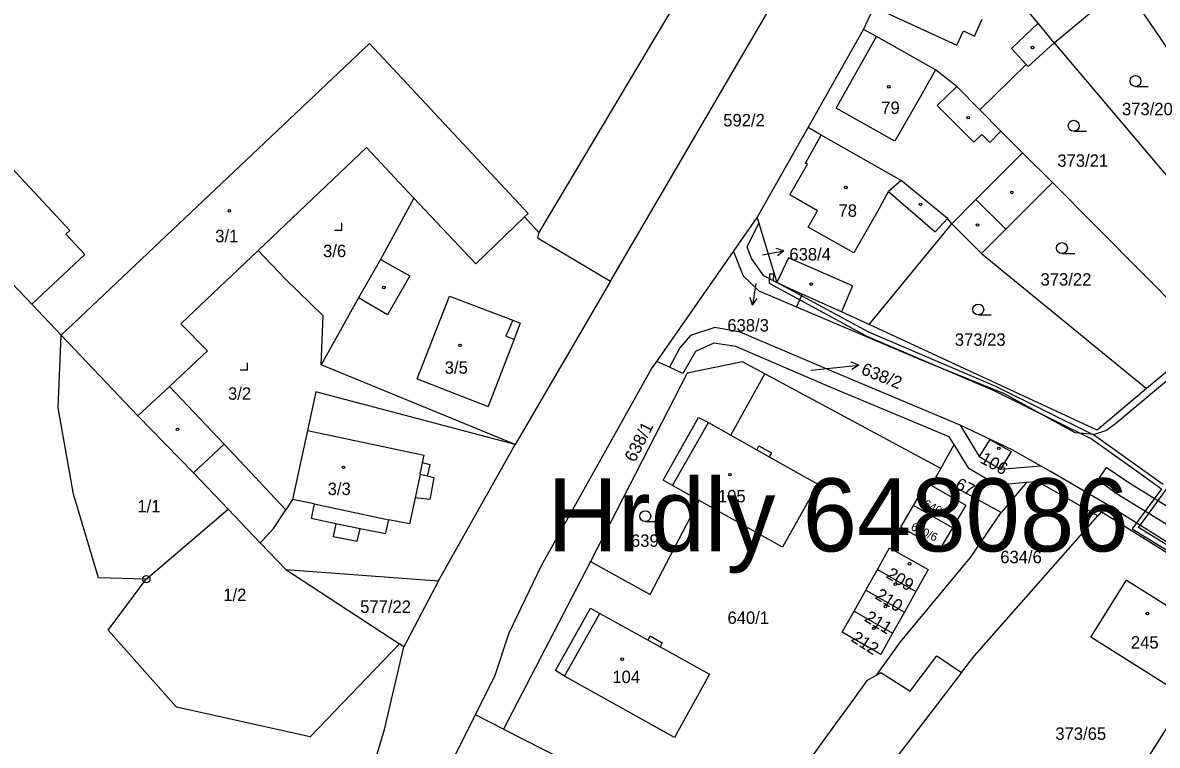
# Model space of a CAD drawing. Extents: x -758582 to -751794, y -998770 to -994350.
# Drawn here: x -754496.6 to -754341.3, y -996853.5 to -996754.5 of the extents above; entities that cross this region are included whole.
import ezdxf

# ---------------------------------------------------------------- set-up
doc = ezdxf.new("R2010")
doc.units = 0
for name, color, linetype in [('Hranice parcel', 7, 'Continuous'), ('Parcelní čísla', 7, 'Continuous'), ('Pop  PČ popisy', 7, 'Continuous'), ('Vnitřní kresba', 7, 'Continuous'), ('Věcná břemena k části', 7, 'Continuous'), ('Značky bodu BP', 7, 'Continuous'), ('Značky budov', 7, 'Continuous'), ('Značky kultur', 7, 'Continuous')]:
    doc.layers.add(name, color=color, linetype=linetype)

msp = doc.modelspace()

# ---------------------------------------------------------------- linework, layer by layer
at = {"layer": 'Hranice parcel'}
for p, q in [((-754381.5, -996755.49), (-754377.61, -996747.1)), ((-754355.4, -996757.29), (-754345.87, -996749.35)), ((-754345.87, -996749.35), (-754319.46, -996788.44)), ((-754416.14, -996789.92), (-754392.89, -996750.08)), ((-754389.1, -996768.87), (-754381.5, -996755.49)), ((-754355.4, -996757.29), (-754325.8, -996792.38)), ((-754396.07, -996781.23), (-754389.1, -996768.87)), ((-754355.66, -996776.42), (-754334.53, -996797.73)), ((-754399.32, -996785.89), (-754396.07, -996781.23)), ((-754396.07, -996781.23), (-754395.84, -996781.98)), ((-754395.84, -996781.98), (-754393.39, -996790.11)), ((-754380.75, -996795.88), (-754369.44, -996782.07)), ((-754369.44, -996782.07), (-754365.35, -996786.16)), ((-754409.82, -996800.93), (-754399.32, -996785.89)), ((-754365.35, -996786.16), (-754342.79, -996804.64)), ((-754416.14, -996789.92), (-754429.19, -996812.29)), ((-754495.35, -996793.06), (-754498.09, -996790.19)), ((-754393.39, -996790.11), (-754389.93, -996791.69)), ((-754495.35, -996793.06), (-754491.31, -996797.33)), ((-754389.93, -996791.69), (-754390.68, -996793.43)), ((-754334.53, -996797.73), (-754342.79, -996804.64)), ((-754429.19, -996812.29), (-754455.74, -996801.38)), ((-754408.09, -996801.72), (-754409.82, -996800.93)), ((-754399.66, -996811.01), (-754395, -996802.63)), ((-754370.91, -996815.57), (-754395, -996802.63)), ((-754402.75, -996809.27), (-754399.66, -996811.01)), ((-754399.66, -996811.01), (-754396.11, -996813.01)), ((-754369.13, -996812.31), (-754369.8, -996811.23)), ((-754439.66, -996830.97), (-754429.19, -996812.29)), ((-754370.91, -996815.57), (-754369.13, -996812.31)), ((-754367.12, -996815.56), (-754369.13, -996812.31)), ((-754371.55, -996816.73), (-754370.91, -996815.57)), ((-754403.99, -996819.96), (-754407.65, -996817.92)), ((-754362.67, -996821.61), (-754371.55, -996816.73)), ((-754359.22, -996817.51), (-754362.67, -996821.61)), ((-754392.59, -996826.34), (-754403.99, -996819.96)), ((-754369.32, -996823.68), (-754374.67, -996820.66)), ((-754348.14, -996820.55), (-754349, -996821.53)), ((-754479.67, -996830.73), (-754468.46, -996821.15)), ((-754468.46, -996821.15), (-754464.08, -996825.74)), ((-754349, -996821.53), (-754349.46, -996822.06)), ((-754329.23, -996833.87), (-754349, -996821.53)), ((-754464.08, -996825.74), (-754460.57, -996829.41)), ((-754418.89, -996828.29), (-754430.77, -996851.24)), ((-754460.57, -996829.41), (-754439.66, -996830.97)), ((-754460.57, -996829.41), (-754445.01, -996839.58)), ((-754381.18, -996832.22), (-754379.61, -996829.41)), ((-754379.61, -996829.41), (-754374.34, -996832.4)), ((-754439.66, -996830.97), (-754444.42, -996839.97)), ((-754382.78, -996835.09), (-754381.18, -996832.22)), ((-754381.18, -996832.22), (-754375.92, -996835.23)), ((-754374.34, -996832.4), (-754375.92, -996835.23)), ((-754382.78, -996835.09), (-754377.53, -996838.12)), ((-754329.23, -996833.87), (-754354.52, -996874.08)), ((-754375.92, -996835.23), (-754377.53, -996838.12)), ((-754444.42, -996839.97), (-754445.01, -996839.58)), ((-754379.7, -996843.82), (-754376.45, -996839.3)), ((-754434.63, -996849.28), (-754431.92, -996843.89)), ((-754380.97, -996844.56), (-754379.7, -996843.82)), ((-754368.1, -996843.52), (-754379.89, -996858.86)), ((-754379.7, -996843.82), (-754379.15, -996843.49)), ((-754437.45, -996854.9), (-754434.63, -996849.28)), ((-754430.77, -996851.24), (-754434.63, -996849.28)), ((-754430.77, -996851.24), (-754407.49, -996863.07))]:
    msp.add_line(p, q, dxfattribs=at)
for points in [[(-754517.71, -996734.79), (-754521.88, -996738.79), (-754520.85, -996739.93), (-754523.11, -996742.06), (-754524.18, -996740.92), (-754527.46, -996744.01), (-754511.37, -996761.27), (-754510.88, -996760.84), (-754509.34, -996762.49), (-754509.43, -996762.58), (-754507.38, -996764.77), (-754507.28, -996764.69), (-754505.78, -996766.3), (-754506.25, -996766.72), (-754504.11, -996769.04), (-754503.6, -996768.55), (-754490.16, -996782.99), (-754490.7, -996783.49), (-754488.08, -996786.29), (-754495.35, -996793.06)], [(-754355.4, -996757.29), (-754357.61, -996754.59), (-754363.42, -996747.76), (-754363.98, -996747.44), (-754373.5, -996743.07), (-754375.4, -996742.32)], [(-754365.61, -996766.47), (-754368.73, -996763.27), (-754371.67, -996761.02), (-754379.73, -996756.44), (-754381.5, -996755.49)], [(-754365.61, -996766.47), (-754359.24, -996760.29), (-754358.99, -996760.54), (-754355.4, -996757.29)], [(-754355.66, -996776.42), (-754359.74, -996772.35), (-754362.7, -996769.38), (-754365.61, -996766.47)], [(-754369.44, -996782.07), (-754370, -996781.34), (-754376.34, -996776.16), (-754387.3, -996769.92), (-754389.1, -996768.87)], [(-754390.68, -996793.43), (-754373.62, -996800.7), (-754362.25, -996805.3), (-754352.6, -996810.64), (-754349.92, -996810.89), (-754348.35, -996810.38), (-754347.02, -996809.4), (-754337.48, -996801.41), (-754332.2, -996797.5), (-754326.06, -996794.06), (-754295.05, -996778.71), (-754292.53, -996777.67), (-754282.39, -996774.8), (-754265.75, -996770.25)], [(-754464.35, -996785.74), (-754449.52, -996771.64), (-754443.07, -996778.55)], [(-754365.35, -996786.16), (-754362.04, -996782.83), (-754355.66, -996776.42)], [(-754443.07, -996778.55), (-754447.63, -996786.98), (-754450.64, -996792.23), (-754455.74, -996801.38)], [(-754443.07, -996778.55), (-754434.56, -996787.55), (-754427.93, -996781.11), (-754425.96, -996783.25), (-754426.14, -996784), (-754416.14, -996789.92)], [(-754393.39, -996790.11), (-754395.16, -996789.21), (-754396.85, -996786.82), (-754397.42, -996785.22), (-754395.84, -996781.98)], [(-754460.58, -996821.22), (-754469.02, -996812.26), (-754476.49, -996804.33), (-754471.32, -996799.46), (-754474.94, -996795.78), (-754464.35, -996785.74)], [(-754455.74, -996801.38), (-754455.48, -996794.68), (-754460.68, -996789.59), (-754464.35, -996785.74)], [(-754399.32, -996785.89), (-754397.98, -996789.21), (-754395.86, -996791.27), (-754390.68, -996793.43)], [(-754380.75, -996795.88), (-754384.53, -996794.15), (-754389.93, -996791.69)], [(-754368.28, -996809.64), (-754385.54, -996802.4), (-754398.39, -996796.89), (-754401.87, -996796.26), (-754405.18, -996797.35), (-754406.65, -996799.04), (-754408.09, -996801.72)], [(-754342.79, -996804.64), (-754349.54, -996810.31), (-754380.75, -996795.88)], [(-754479.67, -996830.73), (-754486.23, -996830.54), (-754489.63, -996819.1), (-754491.73, -996807.27), (-754491.31, -996797.33)], [(-754491.31, -996797.33), (-754480.81, -996808.35), (-754473.2, -996816.19), (-754468.46, -996821.15)], [(-754369.8, -996811.23), (-754386.16, -996804.38), (-754399, -996798.89), (-754402.02, -996798.4), (-754404.53, -996799.55), (-754406.22, -996802.57), (-754408.09, -996801.72)], [(-754431.92, -996843.89), (-754429.99, -996838.09), (-754425.58, -996828.86), (-754410.51, -996801.92), (-754409.82, -996800.93)], [(-754395, -996802.63), (-754398.09, -996800.97), (-754405.67, -996802.54), (-754418.89, -996828.29)], [(-754429.19, -996812.29), (-754456.49, -996805.1), (-754457.63, -996810.36), (-754459.65, -996819.8), (-754460.58, -996821.22)], [(-754407.65, -996817.92), (-754408.92, -996817.15), (-754404.08, -996808.58), (-754402.75, -996809.27)], [(-754368.28, -996809.64), (-754365.67, -996813.93), (-754362.75, -996815.66), (-754357.28, -996815.21)], [(-754357.28, -996815.21), (-754361.16, -996813.03), (-754368.28, -996809.64)], [(-754396.11, -996813.01), (-754395.82, -996812.49), (-754394.12, -996813.44), (-754394.43, -996813.99), (-754387.76, -996817.73), (-754392.59, -996826.34)], [(-754359.22, -996817.51), (-754363.2, -996817.84), (-754367.12, -996815.56)], [(-754348.14, -996820.55), (-754355.84, -996816.05), (-754357.28, -996815.21)], [(-754374.67, -996820.66), (-754372.86, -996817.56), (-754367.49, -996820.58), (-754369.32, -996823.68)], [(-754349.46, -996822.06), (-754357.49, -996817.49), (-754357.69, -996817.38), (-754359.22, -996817.51)], [(-754418.89, -996828.29), (-754410.71, -996832.84), (-754403.99, -996819.96)], [(-754369.32, -996823.68), (-754371.06, -996826.63), (-754376.41, -996823.62), (-754374.67, -996820.66)], [(-754334.3, -996829.22), (-754348.14, -996820.55)], [(-754464.08, -996825.74), (-754463.74, -996825.38), (-754462.25, -996823.8), (-754460.58, -996821.22)], [(-754376.45, -996839.3), (-754366.87, -996827.76), (-754362.67, -996821.61)], [(-754368.1, -996843.52), (-754366.36, -996841.26), (-754349.46, -996822.06)], [(-754379.61, -996829.41), (-754377.96, -996826.42), (-754372.67, -996829.41), (-754374.34, -996832.4)], [(-754445.01, -996839.58), (-754457.25, -996852.33), (-754475.56, -996848.24), (-754484.91, -996837.71), (-754479.67, -996830.73)], [(-754339.16, -996845.73), (-754342.63, -996843.55), (-754350.41, -996838.66), (-754345.5, -996830.87), (-754337.71, -996835.75), (-754334.26, -996837.93), (-754339.16, -996845.73)], [(-754418.9, -996834.7), (-754417.6, -996835.41), (-754410.98, -996839.06), (-754410.72, -996838.5), (-754409.06, -996839.45), (-754409.34, -996839.97), (-754402.58, -996843.74), (-754407.39, -996852.42), (-754422.44, -996844.01), (-754423.69, -996843.25), (-754418.9, -996834.7)], [(-754377.53, -996838.12), (-754379.16, -996841.04), (-754384.45, -996837.99), (-754382.78, -996835.09)], [(-754457.7, -996890.51), (-754455.89, -996880.72), (-754447.09, -996851.31), (-754444.42, -996839.97)], [(-754379.15, -996843.49), (-754375.13, -996846.08), (-754371.48, -996841.21), (-754368.1, -996843.52)], [(-754393.91, -996862.42), (-754391.73, -996859.41), (-754389.61, -996856.49), (-754387.47, -996853.53), (-754385.31, -996850.55), (-754383.17, -996847.6), (-754380.97, -996844.56)]]:
    msp.add_lwpolyline(points, dxfattribs=at)
at = {"layer": 'Pop  PČ popisy'}
for p, q in [((-754395.35, -996786.31), (-754392.4, -996785.79)), ((-754392.4, -996785.79), (-754393.47, -996785.47)), ((-754392.4, -996785.79), (-754393.29, -996786.46)), ((-754396.23, -996790.27), (-754396.7, -996793.23)), ((-754396.7, -996793.23), (-754397.04, -996792.17)), ((-754396.7, -996793.23), (-754396.05, -996792.32)), ((-754388.74, -996802.11), (-754385.15, -996801.75)), ((-754385.15, -996801.75), (-754382.17, -996801.44)), ((-754382.17, -996801.44), (-754383.21, -996801.04)), ((-754382.17, -996801.44), (-754383.11, -996802.04))]:
    msp.add_line(p, q, dxfattribs=at)
at = {"layer": 'Vnitřní kresba'}
for p, q in [((-754407.32, -996752.03), (-754425.96, -996783.25)), ((-754378.27, -996753.23), (-754368.74, -996757.63)), ((-754366.31, -996756.38), (-754365.26, -996754.05)), ((-754368.74, -996757.63), (-754367.83, -996755.67)), ((-754367.83, -996755.67), (-754366.31, -996756.38)), ((-754357.61, -996754.59), (-754361.27, -996758.07)), ((-754491.31, -996797.33), (-754449.14, -996757.39)), ((-754449.14, -996757.39), (-754427.41, -996780.66)), ((-754385.26, -996766.24), (-754379.73, -996756.44)), ((-754359.24, -996760.29), (-754361.27, -996758.07)), ((-754371.67, -996761.02), (-754373.54, -996764.33)), ((-754368.73, -996763.27), (-754371.42, -996765.89)), ((-754373.54, -996764.33), (-754377.24, -996770.78)), ((-754377.24, -996770.78), (-754385.26, -996766.24)), ((-754371.42, -996765.89), (-754366.4, -996770.91)), ((-754366.4, -996770.91), (-754365.33, -996769.84)), ((-754365.33, -996769.84), (-754364.23, -996770.94)), ((-754364.23, -996770.94), (-754362.82, -996769.5)), ((-754362.82, -996769.5), (-754362.7, -996769.38)), ((-754389.46, -996773.76), (-754387.3, -996769.92)), ((-754366.13, -996778.74), (-754359.85, -996772.46)), ((-754359.85, -996772.46), (-754359.74, -996772.35)), ((-754391.59, -996778.12), (-754389.19, -996773.9)), ((-754389.19, -996773.9), (-754389.46, -996773.76)), ((-754376.34, -996776.16), (-754378.1, -996777.64)), ((-754387.81, -996780.28), (-754391.59, -996778.12)), ((-754379.18, -996779.67), (-754378.1, -996777.64)), ((-754378.1, -996777.64), (-754371.7, -996783.18)), ((-754369.44, -996782.07), (-754366.13, -996778.74)), ((-754366.13, -996778.74), (-754362.04, -996782.83)), ((-754427.41, -996780.66), (-754427.93, -996781.11)), ((-754389.08, -996782.52), (-754387.81, -996780.28)), ((-754379.18, -996779.67), (-754382.86, -996786.04)), ((-754371.7, -996783.18), (-754370, -996781.34)), ((-754382.86, -996786.04), (-754389.08, -996782.52)), ((-754391.76, -996786.73), (-754393.39, -996790.11)), ((-754383.01, -996790.57), (-754391.76, -996786.73)), ((-754447.63, -996786.98), (-754443.6, -996789.18)), ((-754443.6, -996789.18), (-754446.65, -996794.54)), ((-754383.01, -996790.57), (-754384.53, -996794.15)), ((-754446.65, -996794.54), (-754450.64, -996792.23)), ((-754442.59, -996803.32), (-754438.18, -996791.96)), ((-754438.18, -996791.96), (-754429.53, -996795.28)), ((-754429.53, -996795.28), (-754430.47, -996797.44)), ((-754429.53, -996795.28), (-754428.51, -996795.69)), ((-754428.51, -996795.69), (-754429.31, -996797.89)), ((-754430.47, -996797.44), (-754429.31, -996797.89)), ((-754429.31, -996797.89), (-754432.87, -996807.07)), ((-754442.59, -996803.32), (-754432.87, -996807.07)), ((-754476.49, -996804.33), (-754480.81, -996808.35)), ((-754407.65, -996817.92), (-754402.75, -996809.27)), ((-754457.63, -996810.36), (-754441.65, -996813.73)), ((-754364.23, -996811.61), (-754365.67, -996813.93)), ((-754364.23, -996811.61), (-754361.32, -996813.27)), ((-754469.02, -996812.26), (-754473.2, -996816.19)), ((-754396.11, -996813.01), (-754394.43, -996813.99)), ((-754361.32, -996813.27), (-754362.75, -996815.66)), ((-754442.19, -996816.41), (-754441.85, -996814.81)), ((-754441.85, -996814.81), (-754441.65, -996813.73)), ((-754440.83, -996815.09), (-754441.85, -996814.81)), ((-754442.19, -996816.41), (-754442.87, -996819.59)), ((-754441.21, -996816.63), (-754442.19, -996816.41)), ((-754441.21, -996816.63), (-754440.83, -996815.09)), ((-754440.27, -996816.84), (-754441.21, -996816.63)), ((-754440.84, -996819.81), (-754440.27, -996816.84)), ((-754456.69, -996820.43), (-754459.65, -996819.8)), ((-754456.69, -996820.43), (-754457.1, -996822.42)), ((-754456.69, -996820.43), (-754446.49, -996822.59)), ((-754442.87, -996819.59), (-754443.65, -996823.16)), ((-754440.84, -996819.81), (-754442.87, -996819.59)), ((-754453.75, -996823.13), (-754457.1, -996822.42)), ((-754446.95, -996824.51), (-754446.49, -996822.59)), ((-754443.65, -996823.16), (-754446.49, -996822.59)), ((-754453.75, -996823.13), (-754454.09, -996824.87)), ((-754450.42, -996823.83), (-754453.75, -996823.13)), ((-754450.83, -996825.54), (-754450.42, -996823.83)), ((-754446.95, -996824.51), (-754450.42, -996823.83)), ((-754454.09, -996824.87), (-754450.83, -996825.54)), ((-754422.44, -996844.01), (-754417.6, -996835.41)), ((-754410.98, -996839.06), (-754409.34, -996839.97))]:
    msp.add_line(p, q, dxfattribs=at)
at = {"layer": 'Věcná břemena k části'}
for points in [[(-754340.49, -996817.78), (-754343.02, -996815.98), (-754350.05, -996810.97), (-754350.19, -996810.9), (-754363.42, -996804.35), (-754380.78, -996796.91), (-754393.39, -996790.11), (-754393.82, -996789.88), (-754393.79, -996788.98), (-754394.39, -996788.96), (-754394.42, -996790.19), (-754381.04, -996797.45), (-754363.68, -996804.89), (-754350.67, -996811.33), (-754350.35, -996811.49), (-754343.5, -996816.37), (-754340.73, -996818.35), (-754342.88, -996821.27), (-754344.74, -996823.82), (-754329.16, -996833.4)], [(-754330.8, -996826.42), (-754345.05, -996817.62), (-754348.32, -996815.43), (-754349.46, -996817.14), (-754346.82, -996819.05), (-754331.85, -996828.2)], [(-754328.5, -996833.1), (-754343.88, -996823.64), (-754342.35, -996821.57), (-754340.03, -996818.41)]]:
    msp.add_lwpolyline(points, dxfattribs=at)
at = {"layer": 'Značky bodu BP'}
for radius in [0.5, 0.0303]:
    msp.add_circle((-754479.67, -996830.73), radius, dxfattribs=at)
at = {"layer": 'Značky budov'}
for centre in [(-754358.39, -996757.94), (-754378.05, -996763.32), (-754367.2, -996767.55), (-754383.94, -996777.11), (-754361.23, -996777.78), (-754468.31, -996780.3), (-754373.72, -996779.42), (-754365.92, -996782.24), (-754447.15, -996790.8), (-754388.67, -996790.33), (-754436.73, -996798.71), (-754475.4, -996810.21), (-754362.99, -996812.82), (-754452.69, -996815.41), (-754399.8, -996816.42), (-754375.22, -996828.63), (-754377.16, -996831.41), (-754378.52, -996834.47), (-754342.66, -996835.43), (-754380.11, -996837.46), (-754414.54, -996841.67)]:
    msp.add_circle(centre, 0.175, dxfattribs=at)
at = {"layer": 'Značky kultur'}
for p, q in [((-754344.29, -996763.27), (-754342.54, -996763.27)), ((-754352.74, -996769.41), (-754350.99, -996769.41)), ((-754452.92, -996782.95), (-754452.92, -996781.95)), ((-754453.92, -996782.95), (-754452.92, -996782.95)), ((-754354.36, -996786.15), (-754352.61, -996786.15)), ((-754365.81, -996794.56), (-754364.06, -996794.56)), ((-754466.81, -996802.09), (-754465.81, -996802.09)), ((-754465.81, -996802.09), (-754465.81, -996801.09)), ((-754411.39, -996822.85), (-754409.64, -996822.85))]:
    msp.add_line(p, q, dxfattribs=at)
for centre in [(-754344.29, -996762.52), (-754352.74, -996768.66), (-754354.36, -996785.4), (-754365.81, -996793.81), (-754411.39, -996822.1)]:
    msp.add_circle(centre, 0.75, dxfattribs=at)

# ---------------------------------------------------------------- texts
at = {"layer": 'Parcelní čísla'}
for s, p in [('79', (-754379.09, -996767.04)), ('373/20', (-754346.14, -996767.21)), ('592/2', (-754400.71, -996768.74)), ('373/21', (-754354.99, -996774.27)), ('78', (-754384.94, -996781.12)), ('3/1', (-754470.24, -996784.6)), ('3/6', (-754455.48, -996786.64)), ('638/4', (-754391.66, -996787.09)), ('373/22', (-754357.28, -996790.54)), ('638/3', (-754400.15, -996796.82)), ('373/23', (-754369.02, -996798.78)), ('3/5', (-754438.83, -996802.6)), ('3/2', (-754468.49, -996806.16)), ('3/3', (-754454.85, -996819.21)), ('105', (-754401.44, -996820.21)), ('1/1', (-754480.89, -996821.58)), ('639', (-754413.34, -996826.3)), ('634/6', (-754362.8, -996828.54)), ('1/2', (-754469.14, -996833.72)), ('577/22', (-754450.4, -996835.34)), ('640/1', (-754400.13, -996836.85)), ('245', (-754344.92, -996840.23)), ('104', (-754415.89, -996844.95)), ('373/65', (-754355.26, -996852.72))]:
    msp.add_text(s, height=1.7, dxfattribs=at).set_placement(p)
for s, height, rotation, p in [('638/2', 1.7, 338, (-754381.96, -996802.61)), ('638/1', 1.7, 63, (-754412.81, -996814.83)), ('106', 1.7, 331, (-754365.69, -996814.7)), ('671', 1.7, 333, (-754369.1, -996818.27)), ('640/7', 1.14, 332, (-754373.41, -996820.76)), ('640/6', 1.14, 334, (-754375.14, -996823.93)), ('209', 1.7, 328, (-754378.54, -996830.44)), ('210', 1.7, 328, (-754380.05, -996833.3)), ('211', 1.7, 329, (-754381.51, -996836.38)), ('212', 1.7, 327, (-754383.33, -996839.13))]:
    msp.add_text(s, height=height, rotation=rotation, dxfattribs=at).set_placement(p)
at = {"layer": 'Pop  PČ popisy'}
msp.add_text('Hrdly 648086', height=10, dxfattribs=at).set_placement((-754424.77, -996826.93))

doc.saveas('drawing.dxf')
